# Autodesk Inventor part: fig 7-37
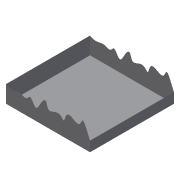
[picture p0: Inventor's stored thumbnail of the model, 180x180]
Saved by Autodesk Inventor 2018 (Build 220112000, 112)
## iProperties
Shininess: 64.0
Length Units: 11269
Angle Units: 11279
Time Units: 11290
Mass Units: 11283
Length Display Precision: 3
Angle Display Precision: 2
Compacted: True
Part Number: fig 7-37
Document SubType Name: Modeling
Created: 2002-12
Designer: deepak
Density: 1 g/cm^3
Material: Generic
Appearance: Default
Density: 0.0
Volumn: 0.0
Area: 0.0
PropertySet Name: Model Information
Control State: 0
Master: False
Checked Out: False
Author: deepak
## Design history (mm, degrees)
sketch "Sketch1"
  geometry: L1 (-32.188, 30.089)-(27.812, 30.089); L2 (27.812, 30.089)-(27.812, -29.911); L3 (27.812, -29.911)-(-32.188, -29.911); L4 (-32.188, -29.911)-(-32.188, 30.089)
  constraints: 8 end point, 2 parallel, 1 horizontal, 1 perpendicular
  dimensions: "d0" = 60 distance of L1.start L1.end; "d1" = 60 distance of L3.end L1.start
extrude "Extrusion1" new body sketch "Sketch1" stored distance "d2" = 20; taper "d3" = 0 deg
sketch "Sketch2"
  geometry: 17 further points
  constraints: 17 other
extrude_surface "ExtrusionSrf1" sketch "Sketch2" dims "d4" = 70, "d5" = 0
split "Split1"
delete_face "Delete Face1"
node "Sketch5"
body "Srf1"
body "Srf2"
